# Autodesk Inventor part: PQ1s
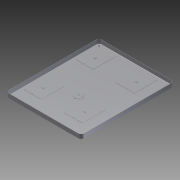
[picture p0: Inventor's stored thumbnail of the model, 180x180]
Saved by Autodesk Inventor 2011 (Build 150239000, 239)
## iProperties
Created: 2015-02
Part Number: PQ1s
Document SubType Name: Modeling
Designer: Evgeny
Density: 1 g/cm^3
Mass: 36.1289 g
Surface Area: 1320.23 cm^2
Volume: 36.1289 cm^3
Author: Evgeny
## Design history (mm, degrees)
sketch "Эскиз1"
  geometry: L1 (-95.8, -110.6)-(-95.8, 110.6); L2 (-88.1, 118.3)-(88.1, 118.3); L3 (95.8, 110.6)-(95.8, -110.6); L4 (88.1, -118.3)-(-88.1, -118.3); C1 r 2 at (-88.1, -110.6); C2 r 2 at (-88.1, 110.6); C3 r 2 at (88.1, 110.6); C4 r 2 at (88.1, -110.6); A1 r 7.7 centre (-88.1, -110.6) between (-95.8, -110.6) and (-88.1, -118.3); A2 r 7.7 centre (-88.1, 110.6) between (-88.1, 118.3) and (-95.8, 110.6); A3 r 7.7 centre (88.1, -110.6) between (88.1, -118.3) and (95.8, -110.6); A4 r 7.7 centre (88.1, 110.6) between (95.8, 110.6) and (88.1, 118.3); 2 further points
  constraints: 8 centre point, 8 end point, 8 point on circle, 8 tangent, 5 coincident, 3 equal radius, 2 parallel, 1 perpendicular
  dimensions: "d0" = 118.3 distance from line of L4 point (0, 0); "d1" = 236.6 distance between parallel lines of L2 L4; "d2" = 95.8 distance from line of L1 point (0, 0); "d3" = 191.6 distance between parallel lines of L3 L1; "d5" = 4 diameter of C1; "d6" = 4 diameter of C2; "d7" = 4 diameter of C3; "d8" = 4 diameter of C4; "d83" = 221.2 distance of A2.centre C1.centre (derived); "d84" = 176.2 distance of A3.centre A1.centre (derived); "d85" = 7.7 radius of A1
extrude "Выдавливание1" new body sketch "Эскиз1" distance "d9" = 0.5; taper "d10" = 0 deg
sketch "Эскиз2"
  geometry: C1 r 4 at (-52.5, 66); C2 r 4 at (52.5, 66); C3 r 4 at (52.5, -66); C4 r 4 at (-52.5, -66); 1 further point
  constraints: 4 centre point, 2 horizontal alignment, 2 vertical alignment
  dimensions: "d11" = 105 distance of C2.centre C1.centre; "d12" = 52.5 horizontal distance of C1.centre point (0, 0); "d13" = 66 vertical distance of C1.centre point (0, 0); "d14" = 132 distance of C4.centre C1.centre; "d15" = 8 diameter of C1; "d16" = 8 diameter of C2; "d17" = 8 diameter of C3; "d18" = 8 diameter of C4
extrude "Выдавливание2" join sketch "Эскиз2" distance "d19" = 14.5; taper "d20" = 0 deg
sketch "Эскиз3"
  geometry: L1 (-23.5, 29)-(23.5, 29); L2 (23.5, 29)-(23.5, -29); L3 (23.5, -29)-(-23.5, -29); L4 (-23.5, -29)-(-23.5, 29); L5 (128.5, 29)-(128.5, -29); L6 (81.5, -29)-(81.5, 29); L7 (81.5, 29)-(128.5, 29); L8 (128.5, -29)-(81.5, -29); L9 (81.5, 103)-(81.5, 161); L10 (81.5, 161)-(128.5, 161); L11 (128.5, 161)-(128.5, 103); L12 (128.5, 103)-(81.5, 103); L13 (23.5, 161)-(23.5, 103); L14 (-23.5, 161)-(23.5, 161); L15 (-23.5, 103)-(-23.5, 161); L16 (23.5, 103)-(-23.5, 103); C1 r 4 at (0, 0) reference; C2 r 4 at (0, 0); C3 r 4 at (0, 132); C4 r 4 at (105, 132); C5 r 4 at (105, 0); C6 r 4 at (0, 0); C7 r 0.6 at (0, 104); C8 r 0.6 at (105, 104); C9 r 0.6 at (0, -28); C10 r 0.6 at (105, -28); 1 further point
  constraints: 32 end point, 9 centre point, 8 collinear, 8 parallel, 6 vertical alignment, 4 horizontal, 4 perpendicular, 3 equal radius, 2 coincident, 2 horizontal alignment
  dimensions: "d27" = 66 vertical distance of C3.centre point (52.5, 66); "d44" = 132 distance of C1.centre C3.centre (derived); "d50" = 1.2 diameter of C9; "d54" = 28 distance of C10.centre C5.centre; "d58" = 28 distance of C8.centre C4.centre; "d72" = 28 distance of C7.centre C3.centre; "d75" = 105 distance of C5.centre C1.centre; "d82" = 28 distance of C9.centre C1.centre; "d91" = 58 distance between parallel lines of L3 L1; "d92" = 29 distance from line of L1 C1.centre; "d93" = 47 distance between parallel lines of L2 L4; "d94" = 23.5 distance from line of L4 C1.centre; "d96" = 47 distance between parallel lines of L5 L6; "d99" = 58 distance between parallel lines of L16 L14; "d101" = 29 distance from line of L14 C3.centre; "d102" = 23.5 distance from line of L6 C5.centre
extrude "Выдавливание4" join sketch "Эскиз3" distance "d59" = 0.5; taper "d60" = 0 deg
sketch "Эскиз4"
  geometry: L1 (3.2, -27)-(3.2, -29); L2 (-3.2, -29)-(-3.2, -27); L3 (-3.2, -27)-(-1.732, -27); L4 (1.732, -27)-(3.2, -27); L5 (3.2, -29)-(1.732, -29); L6 (-1.732, -29)-(-3.2, -29); C1 r 0.6 at (0, -28); A1 r 2 centre (0, -28) between (-1.732, -29) and (1.732, -29); A2 r 2 centre (0, -28) between (1.732, -27) and (-1.732, -27); 1 further point
  constraints: 12 end point, 5 parallel, 4 point on circle, 3 centre point, 2 collinear, 2 horizontal, 2 perpendicular, 1 coincident, 1 vertical alignment
  dimensions: "d62" = 28 distance of A1.centre point (0, 0); "d64" = 1.2 diameter of C1; "d195" = 6.4 distance between parallel lines of L1 L2; "d196" = 3.2 distance from line of L2 A1.centre; "d197" = 2 distance between parallel lines of L6 L3; "d198" = 1 distance from line of L3 A1.centre; "d199" = 2 radius of A2; "d200" = 2 radius of A1
extrude "Выдавливание5" cut sketch "Эскиз4" distance "d65" = 1; taper "d66" = 0 deg
sketch "Эскиз5"
  geometry: C1 r 0.6 at (0, 0) reference; 1 further point
extrude "Выдавливание6" join sketch "Эскиз5" distance "d67" = 4.35; taper "d68" = 0 deg
sketch "Эскиз6"
  geometry: L1 (7.5, 8.718)-(7.5, -8.718); L2 (-7.5, -8.718)-(-7.5, 8.718); C1 r 0.6 at (0, 0) reference; A1 r 11.5 centre (0, 0) between (7.5, 8.718) and (-7.5, 8.718); A2 r 11.5 centre (0, 0) between (-7.5, -8.718) and (7.5, -8.718); 2 further points
  constraints: 4 end point, 4 point on circle, 2 centre point, 1 coincident, 1 parallel, 1 vertical
  dimensions: "d159" = 15 distance between parallel lines of L1 L2; "d160" = 7.5 distance from line of L2 point (0, 0); "d165" = 11.5 radius of A1; "d166" = 11.5 radius of A2
extrude "Выдавливание7" join sketch "Эскиз6" distance "d70" = 0.6; taper "d71" = 0 deg
sketch "Эскиз7"
  geometry: C1 r 2 at (0, -28) reference; C2 r 0.6 at (0, -28); C3 r 1.825 at (0, -28); C4 r 4.5 at (0, -28); 1 further point
  constraints: 3 centre point, 3 coincident
  dimensions: "d86" = 1.2 diameter of C2; "d87" = 3.65 diameter of C3; "d88" = 9 diameter of C4
extrude "Выдавливание8" join sketch "Эскиз7" distance "d89" = 10; taper "d90" = 0 deg
sketch "Эскиз8"
  geometry: L1 (-88.1, 118.3)-(88.1, 118.3); L2 (95.8, 110.6)-(95.8, -110.6); L3 (88.1, -118.3)-(-88.1, -118.3); L4 (-95.8, -110.6)-(-95.8, 110.6); L5 (-88.1, 117.8)-(88.1, 117.8); L6 (95.3, 110.6)-(95.3, -110.6); L7 (88.1, -117.8)-(-88.1, -117.8); L8 (-95.3, -110.6)-(-95.3, 110.6); L9 (-88.1, 118.3)-(88.1, 118.3) reference; L10 (-95.8, -110.6)-(-95.8, 110.6) reference; L11 (88.1, -118.3)-(-88.1, -118.3) reference; L12 (95.8, 110.6)-(95.8, -110.6) reference; A1 r 7.2 centre (-88.1, 110.6) between (-88.1, 117.8) and (-95.3, 110.6); A2 r 7.2 centre (88.1, 110.6) between (95.3, 110.6) and (88.1, 117.8); A3 r 7.2 centre (88.1, -110.6) between (88.1, -117.8) and (95.3, -110.6); A4 r 7.2 centre (-88.1, -110.6) between (-95.3, -110.6) and (-88.1, -117.8); A5 r 7.7 centre (-88.1, 110.6) between (-88.1, 118.3) and (-95.8, 110.6); A6 r 7.7 centre (88.1, 110.6) between (95.8, 110.6) and (88.1, 118.3); A7 r 7.7 centre (88.1, -110.6) between (88.1, -118.3) and (95.8, -110.6); A8 r 7.7 centre (-88.1, -110.6) between (-95.8, -110.6) and (-88.1, -118.3); 1 further point
  constraints: 16 end point, 16 point on circle, 16 tangent, 8 centre point, 6 equal radius, 4 collinear, 4 parallel, 2 horizontal, 2 perpendicular
  dimensions: "d176" = 0.5 distance between parallel lines of L2 L6; "d177" = 0.5 distance between parallel lines of L3 L7; "d178" = 0.5 distance between parallel lines of L4 L8; "d179" = 0.5 distance between parallel lines of L5 L1; "d180" = 7.2 radius of A1; "d181" = 7.7 radius of A5
extrude "Выдавливание9" join sketch "Эскиз8" distance "d138" = 10; taper "d139" = 0 deg
sketch "Эскиз10"
  geometry: C1 r 3.25 at (0, 0); C2 r 3.25 at (0, 132); C3 r 3.25 at (-105, 132); C4 r 3.25 at (-105, 0); 2 further points
  constraints: 4 centre point, 3 equal radius, 2 horizontal alignment, 2 vertical alignment, 1 coincident
  dimensions: "d183" = 6.5 diameter of C1; "d184" = 132 distance of C2.centre point (0, 0); "d185" = 105 distance of C4.centre point (0, 0)
extrude "Выдавливание10" join sketch "Эскиз10" distance "d146" = 1.3; taper "d147" = 0 deg
sketch "Эскиз11"
  geometry: C1 r 0.6 at (0, 0) reference; C2 r 0.6 at (0, 0); 1 further point
  constraints: 1 centre point, 1 coincident, 1 concentric
extrude "Выдавливание11" join sketch "Эскиз11" distance "d163" = 3; taper "d164" = 0 deg
fillet "Сопряжение1" dims "d182" = 0.6
sketch "Эскиз13"
  geometry: C1 r 2 at (0, -28) reference; C2 r 2.4 at (-5.5, -22.5); C3 r 2.4 at (5.5, -22.5); C4 r 2.4 at (5.5, -33.5); C5 r 2.4 at (-5.5, -33.5); 1 further point
  constraints: 4 centre point, 3 equal radius, 2 horizontal alignment, 2 vertical alignment
  dimensions: "d186" = 4.8 diameter of C2; "d187" = 11 distance of C5.centre C2.centre; "d188" = 11 distance of C4.centre C5.centre; "d189" = 5.5 horizontal distance of C5.centre C1.centre; "d190" = 5.5 horizontal distance of C5.centre C1.centre
extrude "Выдавливание13" join sketch "Эскиз13" distance "d191" = 0.5; taper "d192" = 0 deg
fillet "Сопряжение2" dims "d201" = 0.3
node "Твердое тело1"
other parameters: "d61" = 4.05, "d105" = 25, "d106" = 12.5, "d193" = 2, "d194" = 1
